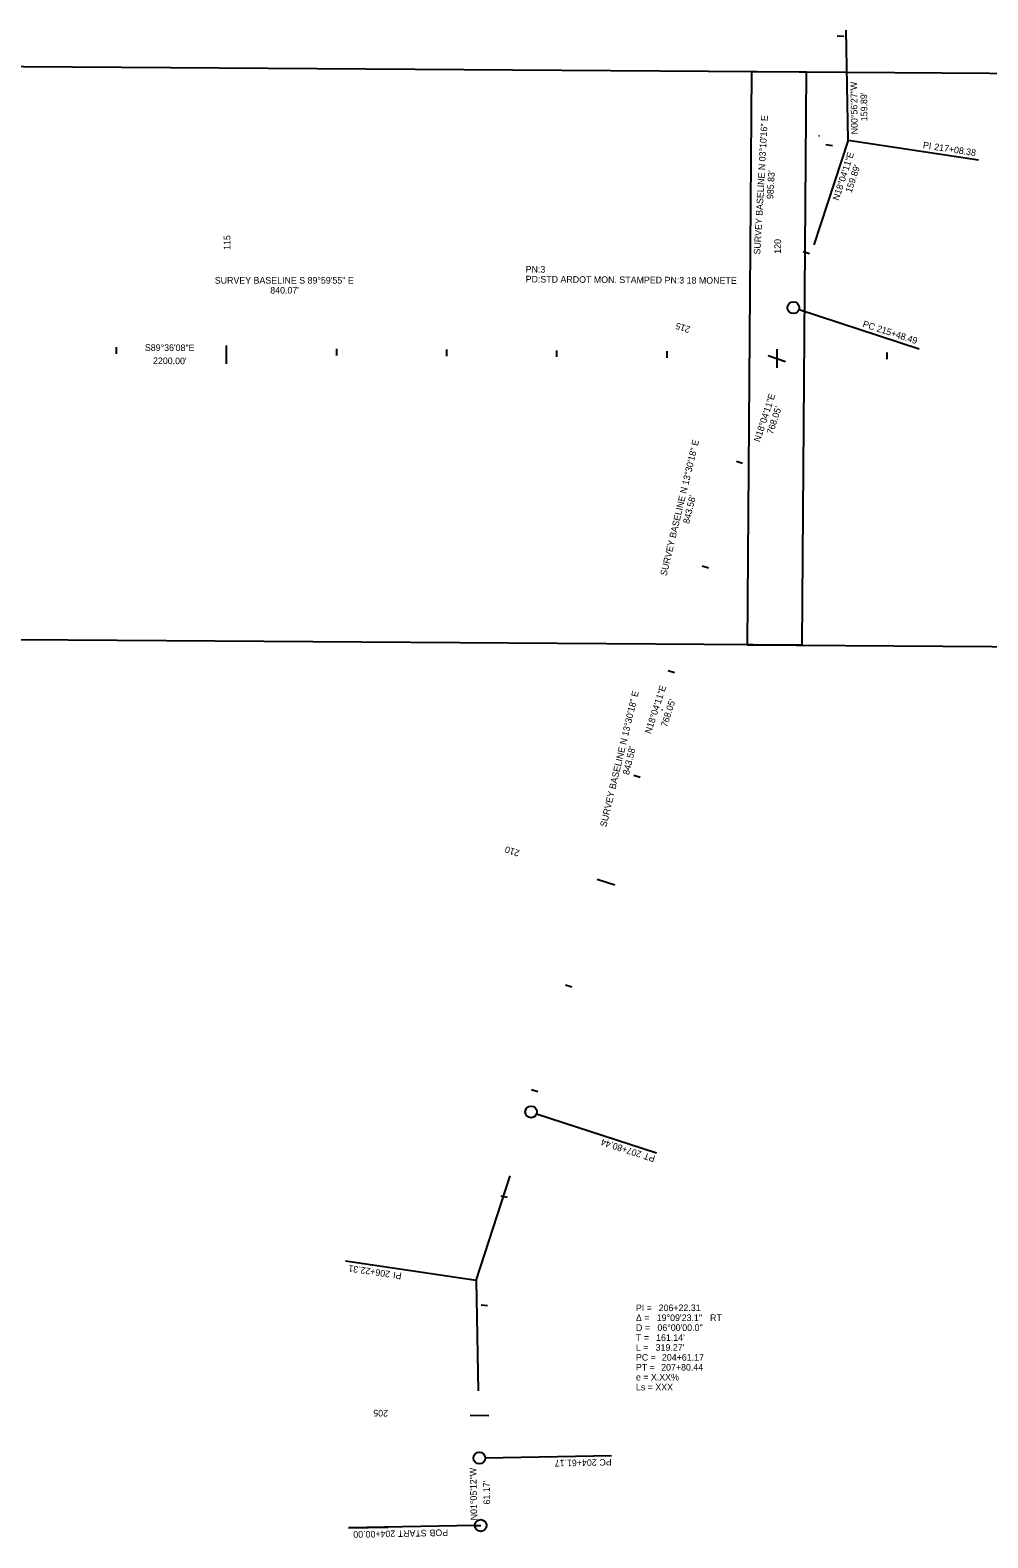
# Model space of a CAD drawing. Extents: x 1801895 to 1805049, y 572742 to 575010.
# Drawn here: x 1802794 to 1803664, y 572742 to 574110 of the extents above; entities that cross this region are included whole.
import ezdxf

# ---------------------------------------------------------------- set-up
doc = ezdxf.new("R2010")
doc.units = 0
for name, color, linetype in [('_CIVIL_CONSTRUCTION', 7, 'Continuous'), ('DSN_DRFT_Named-Boundary', 7, 'Continuous'), ('DSN_RDWY_Alignment Annotation', 7, 'Continuous'), ('DSN_ROW_Point-Annotation', 7, 'Continuous'), ('S_BASELINE_ANNOT', 7, 'Continuous')]:
    doc.layers.add(name, color=color, linetype=linetype)

msp = doc.modelspace()

# ---------------------------------------------------------------- linework, layer by layer
at = {"layer": '_CIVIL_CONSTRUCTION'}
for centre in [(1803510.7, 574014.4), (1803472.2, 573812.3), (1803472.2, 573812.3), (1803368.1, 573493.4), (1803368.1, 573493.4), (1803368.1, 573493.4), (1803368.1, 573493.4), (1803368.1, 573493.4)]:
    msp.add_circle(centre, 0.05, dxfattribs=at)
at = {"layer": 'DSN_DRFT_Named-Boundary'}
for points in [[(1801899, 574083.3), (1801895.4, 573563.3), (1803495.3, 573552.2), (1803499, 574072.2)], [(1803449, 574072.5), (1803445.3, 573552.5), (1805045.3, 573541.4), (1805048.9, 574061.4)]]:
    msp.add_lwpolyline(points, close=True, dxfattribs=at)
at = {"layer": 'DSN_RDWY_Alignment Annotation'}
for p, q in [((1803536.8, 574010.5), (1803535.1, 574110.4)), ((1803527, 574105.3), (1803533, 574105)), ((1803536.8, 574010.5), (1803505.8, 573915.4)), ((1803516.7, 574006.5), (1803522.6, 574005.6)), ((1803536.8, 574010.5), (1803655.4, 573992.6)), ((1803655.4, 573992.6), (1803655.4, 573992.6)), ((1803496, 573909.4), (1803501.8, 573907.8)), ((1803487.2, 573858.4), (1803487.2, 573858.4)), ((1803492.3, 573856.8), (1803601.3, 573821.2)), ((1802872.2, 573822.5), (1802872.2, 573816.5)), ((1802972.2, 573824.2), (1802972.1, 573807.4)), ((1803072.2, 573821.1), (1803072.2, 573815.1)), ((1803172.2, 573820.4), (1803172.2, 573814.4)), ((1803272.2, 573819.7), (1803272.2, 573813.7)), ((1803372.2, 573819), (1803372.2, 573813)), ((1803464.2, 573815), (1803480.1, 573809.7)), ((1803472.2, 573820.7), (1803472.1, 573803.9)), ((1803572.2, 573817.7), (1803572.1, 573811.7)), ((1803601.3, 573821.2), (1803601.3, 573821.2)), ((1803435.4, 573719.1), (1803441.1, 573717.3)), ((1803404.4, 573624.1), (1803410.1, 573622.2)), ((1803373.4, 573529), (1803379.1, 573527.1)), ((1803342.4, 573433.9), (1803348.1, 573432.1)), ((1803309.1, 573339.6), (1803325, 573334.4)), ((1803280.3, 573243.8), (1803286, 573241.9)), ((1803249.3, 573148.7), (1803255, 573146.9)), ((1803249, 573128.3), (1803249, 573128.3)), ((1803254, 573126.6), (1803363, 573091.1)), ((1803363, 573091.1), (1803363, 573091.1)), ((1803199, 572975.1), (1803230, 573070.2)), ((1803221.4, 573052.2), (1803227.3, 573050.8)), ((1803199, 572975.1), (1803080.3, 572992.8)), ((1803080.3, 572992.8), (1803080.3, 572992.8)), ((1803199, 572975.1), (1803200.9, 572875.1)), ((1803203.5, 572953.2), (1803209.5, 572952.5)), ((1803193.7, 572853), (1803210.5, 572852.6)), ((1803202, 572814), (1803202, 572814)), ((1803207.4, 572814.1), (1803322, 572816.3)), ((1803322, 572816.3), (1803322, 572816.3)), ((1803197.9, 572752.7), (1803083.2, 572750.5)), ((1803083.2, 572750.5), (1803119.2, 572751.2)), ((1803197.2, 572752.7), (1803203.2, 572752.8)), ((1803203.2, 572752.8), (1803203.2, 572752.8))]:
    msp.add_line(p, q, dxfattribs=at)
for centre in [(1803487.2, 573858.4), (1803249, 573128.3), (1803202, 572814), (1803203.2, 572752.8)]:
    msp.add_circle(centre, 5.34, dxfattribs=at)

# ---------------------------------------------------------------- texts
at = {"layer": '_CIVIL_CONSTRUCTION'}
for s, rotation, p in [('SURVEY BASELINE N 03°10\'16" E', 86.829, (1803457.1, 573906.6)), ("985.83'", 86.829, (1803468.9, 573956.9)), ('SURVEY BASELINE S 89°59\'55" E', 359.9986, (1802961.7, 573880.3)), ("840.07'", 359.9986, (1803012.1, 573871.3)), ('SURVEY BASELINE N 13°30\'18" E', 76.495, (1803372, 573614.6)), ("843.58'", 76.495, (1803392.6, 573661.9))]:
    msp.add_text(s, height=6, rotation=rotation, dxfattribs=at).set_placement(p)
at = {"layer": 'DSN_DRFT_Named-Boundary'}
for s, p in [('SURVEY BASELINE N 13°30\'18" E', (1803317.3, 573386.6)), ("843.58'", (1803337.9, 573433.9))]:
    msp.add_text(s, height=6, rotation=76.495, dxfattribs=at).set_placement(p)
at = {"layer": 'DSN_RDWY_Alignment Annotation'}
for s, rotation, p in [('N00°56\'27"W', 90.9408, (1803545.7, 574015.9)), ("159.89'", 90.9408, (1803554.5, 574027.8)), ('PI ', 351.4356, (1803604.5, 574003.3)), ('217+08.38', 351.4356, (1803614.8, 574001.7)), ('N18°04\'11"E', 71.9303, (1803528.3, 573955.3)), ("159.89'", 71.9303, (1803540, 573962.3)), ('115', 89.6021, (1802975.8, 573910.9)), ('120', 89.6021, (1803475.8, 573907.4)), ('215', 161.9303, (1803394.1, 573841)), ('PC', 341.9303, (1803549.6, 573841.2)), ('215+48.49', 341.9303, (1803562.4, 573837.1)), ('S89°36\'08"E', 359.6021, (1802898.2, 573819.3)), ('N18°04\'11"E', 71.9303, (1803456.7, 573736)), ("768.05'", 71.9303, (1803468.5, 573743)), ('N18°04\'11"E', 71.9303, (1803357.7, 573471.1)), ('210', 161.9303, (1803239.1, 573365.6)), ('207+80.44', 161.9303, (1803349.8, 573092.2)), ('PT', 161.9303, (1803362.1, 573088.2)), ('206+22.31', 171.5085, (1803121.3, 572983.7)), ('PI ', 171.5085, (1803131.7, 572982.1)), ('205', 178.757, (1803119.1, 572857.6)), ('204+61.17', 181.0867, (1803308.5, 572813)), ('PC', 181.0867, (1803322.1, 572813.3)), ('N01°05\'12"W', 91.0867, (1803200.1, 572757.5)), ('204+00.00', 181.0867, (1803125.6, 572748.3)), ('START', 181.0867, (1803154.1, 572748.9)), ('POB ', 181.0867, (1803173.6, 572749.3))]:
    msp.add_text(s, height=6, rotation=rotation, dxfattribs=at).set_placement(p)
for s, p in [('PI = ', (1803344.2, 572947.4)), ('206+22.31', (1803364.8, 572947.4)), ('Δ = ', (1803344.2, 572938.4)), ('D = ', (1803344.2, 572929.4)), ('19°09\'23.1"', (1803363.1, 572938.4)), ('06°00\'00.0"', (1803363.7, 572929.4)), (' RT', (1803409.3, 572938.4)), ('T = ', (1803344.2, 572920.4)), ("161.14'", (1803362.5, 572920.4)), ('L = ', (1803344.2, 572911.4)), ('PC = ', (1803344.2, 572902.4)), ("319.27'", (1803362.1, 572911.4)), ('204+61.17', (1803367.8, 572902.4)), ('PT = ', (1803344.2, 572893.4)), ('207+80.44', (1803367.1, 572893.4)), ('e = X.XX%', (1803344.2, 572884.4)), ('Ls = XXX', (1803344.2, 572875.4))]:
    msp.add_text(s, height=6, dxfattribs=at).set_placement(p)
at = {"layer": 'DSN_ROW_Point-Annotation'}
for s, rotation, p in [("2200.00'", 359.6021, (1802905.6, 573807.3)), ("768.05'", 71.9303, (1803372.3, 573477.2)), ("61.17'", 91.0867, (1803211.8, 572771.9))]:
    msp.add_text(s, height=6, rotation=rotation, dxfattribs=at).set_placement(p)
at = {"layer": 'S_BASELINE_ANNOT'}
for s, p in [('PN:3', (1803244, 573890.4)), ('PD:STD ARDOT MON. STAMPED PN:3 18 MONETE', (1803244, 573881.4))]:
    msp.add_text(s, height=6, rotation=359.6021, dxfattribs=at).set_placement(p)

doc.saveas('drawing.dxf')
